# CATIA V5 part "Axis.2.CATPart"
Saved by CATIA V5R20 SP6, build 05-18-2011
Part number: Axis.2
Publications: "Center Point", "Line.4(Z Dir)", "Line.5(X Dir)", "Line.6(Y Dir)"
Bounding box of the stored display mesh (mm): x -79 to -39, y 23.5 to 63.5, z -20 to 20
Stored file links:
  C:\Work\#01 CATIA Lecture Materials\#299 TOYOTA CATIA V5\TOYOTA_CATIA\LCS\Solid\Solid EX03\Axis.2.CATPart
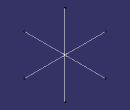
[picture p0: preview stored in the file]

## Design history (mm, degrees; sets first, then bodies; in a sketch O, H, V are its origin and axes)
Set1 "Axis"
  Point1 "Center Point": (-59, 43.5, 0)
  Line1 "Line.4(Z Dir)": type PtDir, RefPoint Point1, Direction xy-plane, Start -20, End 20
  Line2 "Line.5(X Dir)": type PtDir, RefPoint Point1, Direction yz-plane, Start -20, End 20
  Line3 "Line.6(Y Dir)": type PtDir, RefPoint Point1, Direction zx-plane, Start -20, End 20
Body1 (main body)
